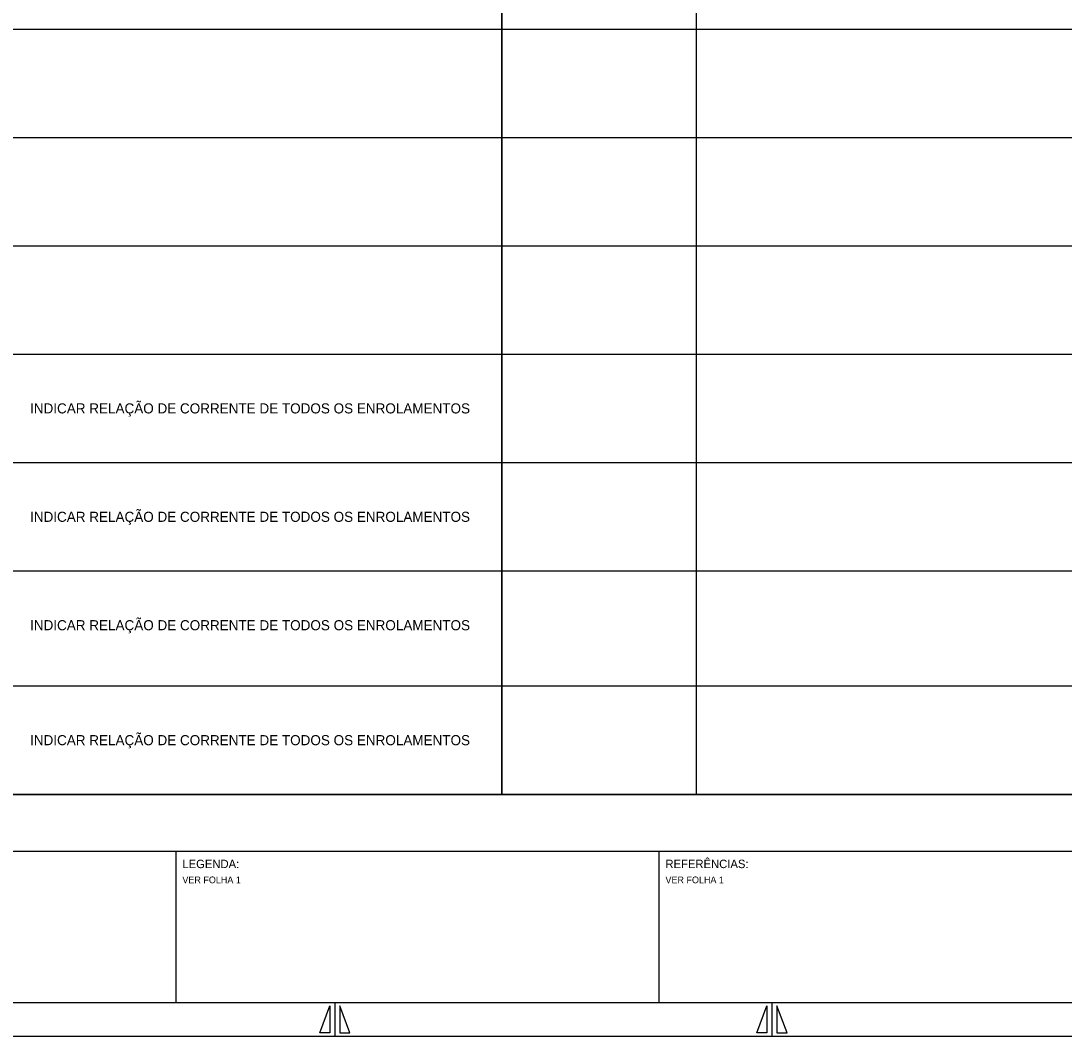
# Model space of a CAD drawing. Extents: x 563 to 3226, y 358 to 960.
# Drawn here: x 1721.5 to 2031.8, y 358 to 659.8 of the extents above; entities that cross this region are included whole.
import ezdxf

# ---------------------------------------------------------------- set-up
doc = ezdxf.new("R2010")
doc.units = 0
doc.layers.add('Default', color=7, linetype='Continuous')
doc.layers.add('New Level (0)', color=7, linetype='Continuous')

msp = doc.modelspace()

# ---------------------------------------------------------------- linework, layer by layer
at = {"layer": 'New Level (0)'}
for p, q in [((1922.37, 925.28), (1922.37, 429.83)), ((1514.44, 657.39), (2214.61, 657.39)), ((1514.44, 625.16), (2214.61, 625.16)), ((1514.44, 592.93), (2214.61, 592.93)), ((1514.44, 560.7), (2214.61, 560.7)), ((1514.44, 528.47), (2214.61, 528.47)), ((1514.44, 528.47), (2214.61, 528.47)), ((1514.44, 496.25), (2214.61, 496.25)), ((1514.44, 462.06), (2214.61, 462.06)), ((1514.44, 429.83), (2214.61, 429.83)), ((1483.88, 412.96), (2304.88, 412.96)), ((1767.55, 412.96), (1767.55, 367.96)), ((1911.21, 412.96), (1911.21, 367.96)), ((1483.88, 367.96), (2304.88, 367.96)), ((1483.88, 367.96), (2304.88, 367.96)), ((1810.38, 358.96), (1813.38, 366.96)), ((1813.38, 366.96), (1813.38, 358.96)), ((1814.88, 367.96), (1814.88, 357.96)), ((1816.38, 366.96), (1816.38, 358.96)), ((1819.38, 358.96), (1816.38, 366.96)), ((1940.38, 358.96), (1943.38, 366.96)), ((1943.38, 366.96), (1943.38, 358.96)), ((1944.88, 367.96), (1944.88, 357.96)), ((1946.38, 366.96), (1946.38, 358.96)), ((1949.38, 358.96), (1946.38, 366.96)), ((1473.88, 357.96), (2314.88, 357.96)), ((1473.88, 357.96), (2314.88, 357.96)), ((1813.38, 358.96), (1810.38, 358.96)), ((1816.38, 358.96), (1819.38, 358.96)), ((1943.38, 358.96), (1940.38, 358.96)), ((1946.38, 358.96), (1949.38, 358.96))]:
    msp.add_line(p, q, dxfattribs=at)
for points in [[(1718.4, 915.21), (1864.53, 915.21), (1864.53, 429.83), (1718.4, 429.83)], [(1864.53, 915.21), (2068.49, 915.21), (2068.49, 429.83), (1864.53, 429.83)]]:
    msp.add_lwpolyline(points, close=True, dxfattribs=at)

# ---------------------------------------------------------------- texts
at = {"layer": 'Default'}
for p in [(1724.25, 543.09), (1724.25, 510.86), (1724.25, 478.63), (1724.25, 444.45)]:
    msp.add_text('INDICAR RELAÇÃO DE CORRENTE DE TODOS OS ENROLAMENTOS', height=3, dxfattribs=at).set_placement(p)
at = {"layer": 'New Level (0)'}
for s, height, p in [('LEGENDA:', 2.5, (1769.55, 407.91)), ('REFERÊNCIAS:', 2.5, (1913.21, 407.91)), ('VER FOLHA 1', 2, (1769.55, 403.41)), ('VER FOLHA 1', 2, (1913.21, 403.41))]:
    msp.add_text(s, height=height, dxfattribs=at).set_placement(p)

doc.saveas('drawing.dxf')
